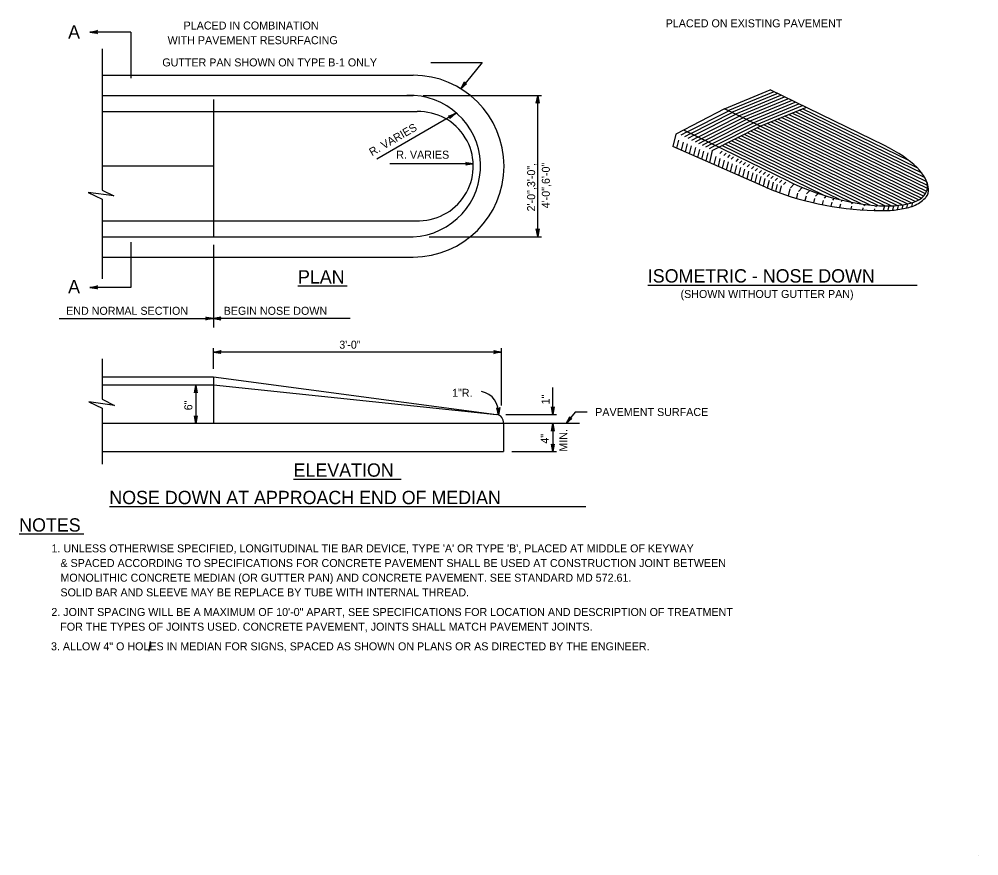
# Model space of a CAD drawing. Extents: x -7.6 to -0.4, y 98.1 to 108.3.
# Drawn here: x -7.55 to -0.36, y 98.11 to 104.38 of the extents above; entities that cross this region are included whole.
import ezdxf

# ---------------------------------------------------------------- set-up
doc = ezdxf.new("R2010")
doc.units = 0
for name, color, linetype in [('DETL-DIMS', 7, 'Continuous'), ('DETL-LINE', 7, 'Continuous'), ('DETL-NOTE', 7, 'Continuous'), ('DETL-PATT', 7, 'Continuous'), ('DETL-TITL', 7, 'Continuous'), ('TTLB-TEXT', 7, 'Continuous')]:
    doc.layers.add(name, color=color, linetype=linetype)

msp = doc.modelspace()

# ---------------------------------------------------------------- linework, layer by layer
at = {"layer": 'DETL-DIMS'}
for p, q in [((-6.7176, 104.2848), (-7.0248, 104.2848)), ((-6.7176, 104.2848), (-6.7176, 103.9375)), ((-4.4689, 104.0567), (-4.0849, 104.0567)), ((-4.0849, 104.0567), (-4.245, 103.8594)), ((-4.5276, 103.8092), (-3.6412, 103.8092)), ((-3.6685, 102.7486), (-3.6685, 103.8092)), ((-4.875, 103.3346), (-4.2738, 103.6817)), ((-4.1696, 103.2952), (-4.7761, 103.2952)), ((-4.4813, 102.7486), (-3.6412, 102.7486)), ((-6.7176, 102.7088), (-6.7176, 102.3698)), ((-6.0991, 102.688), (-6.0991, 102.0696)), ((-6.7176, 102.3698), (-7.0248, 102.3698)), ((-7.2552, 102.1357), (-6.0991, 102.1357)), ((-5.0737, 102.1357), (-6.0991, 102.1357)), ((-6.0991, 101.7591), (-6.0991, 101.9135)), ((-3.9396, 101.8843), (-6.0991, 101.8843)), ((-3.9396, 101.4848), (-3.9396, 101.9135)), ((-6.2305, 101.6379), (-6.2305, 101.35)), ((-3.555, 101.4168), (-3.555, 101.6185)), ((-3.3885, 101.4349), (-3.4563, 101.35)), ((-3.298, 101.4349), (-3.3885, 101.4349)), ((-3.9072, 101.4168), (-3.5278, 101.4168)), ((-3.555, 101.35), (-3.555, 101.1379)), ((-3.8636, 101.1379), (-3.5278, 101.1379))]:
    msp.add_line(p, q, dxfattribs=at)
for points in [[(-7.0248, 104.2848), (-6.9683, 104.2954), (-6.9727, 104.2924), (-6.9749, 104.2886), (-6.9755, 104.2848), (-6.9749, 104.2811), (-6.9727, 104.2773), (-6.9683, 104.2742), (-7.0248, 104.2848), (-6.9727, 104.2773), (-6.9749, 104.2811), (-7.0248, 104.2848), (-6.9755, 104.2848), (-6.9749, 104.2886), (-7.0248, 104.2848), (-6.9727, 104.2924)], [(-4.245, 103.8594), (-4.2176, 103.91), (-4.218, 103.9047), (-4.2165, 103.9006), (-4.214, 103.8977), (-4.2106, 103.8958), (-4.2063, 103.8951), (-4.2012, 103.8966), (-4.245, 103.8594), (-4.2063, 103.8951), (-4.2106, 103.8958), (-4.245, 103.8594), (-4.214, 103.8977), (-4.2165, 103.9006), (-4.245, 103.8594), (-4.218, 103.9047)], [(-3.6685, 103.8068), (-3.6579, 103.7503), (-3.6609, 103.7547), (-3.6647, 103.7569), (-3.6685, 103.7576), (-3.6723, 103.7569), (-3.676, 103.7547), (-3.6791, 103.7503), (-3.6685, 103.8068), (-3.676, 103.7547), (-3.6723, 103.7569), (-3.6685, 103.8068), (-3.6685, 103.7576), (-3.6647, 103.7569), (-3.6685, 103.8068), (-3.6609, 103.7547)], [(-4.2835, 103.6739), (-4.3271, 103.6364), (-4.3248, 103.6412), (-4.3248, 103.6456), (-4.3261, 103.6492), (-4.3285, 103.6522), (-4.3324, 103.6543), (-4.3377, 103.6548), (-4.2835, 103.6739), (-4.3324, 103.6543), (-4.3285, 103.6522), (-4.2835, 103.6739), (-4.3261, 103.6492), (-4.3248, 103.6456), (-4.2835, 103.6739), (-4.3248, 103.6412)], [(-4.1514, 103.295), (-4.208, 103.285), (-4.2036, 103.288), (-4.2013, 103.2918), (-4.2006, 103.2955), (-4.2012, 103.2993), (-4.2034, 103.3031), (-4.2077, 103.3062), (-4.1514, 103.295), (-4.2034, 103.3031), (-4.2012, 103.2993), (-4.1514, 103.295), (-4.2006, 103.2955), (-4.2013, 103.2918), (-4.1514, 103.295), (-4.2036, 103.288)], [(-3.6685, 102.751), (-3.6791, 102.8075), (-3.676, 102.8031), (-3.6723, 102.8009), (-3.6685, 102.8002), (-3.6647, 102.8009), (-3.6609, 102.8031), (-3.6579, 102.8075), (-3.6685, 102.751), (-3.6609, 102.8031), (-3.6647, 102.8009), (-3.6685, 102.751), (-3.6685, 102.8002), (-3.6723, 102.8009), (-3.6685, 102.751), (-3.676, 102.8031)], [(-7.0248, 102.3698), (-6.9683, 102.3804), (-6.9727, 102.3774), (-6.9749, 102.3736), (-6.9755, 102.3698), (-6.9749, 102.366), (-6.9727, 102.3622), (-6.9683, 102.3592), (-7.0248, 102.3698), (-6.9727, 102.3622), (-6.9749, 102.366), (-7.0248, 102.3698), (-6.9755, 102.3698), (-6.9749, 102.3736), (-7.0248, 102.3698), (-6.9727, 102.3774)], [(-6.0991, 102.1357), (-6.1556, 102.1251), (-6.1512, 102.1281), (-6.149, 102.1319), (-6.1483, 102.1357), (-6.149, 102.1395), (-6.1512, 102.1433), (-6.1556, 102.1463), (-6.0991, 102.1357), (-6.1512, 102.1433), (-6.149, 102.1395), (-6.0991, 102.1357), (-6.1483, 102.1357), (-6.149, 102.1319), (-6.0991, 102.1357), (-6.1512, 102.1281)], [(-6.0991, 102.1357), (-6.0426, 102.1251), (-6.0469, 102.1281), (-6.0492, 102.1319), (-6.0498, 102.1357), (-6.0492, 102.1395), (-6.0469, 102.1433), (-6.0426, 102.1463), (-6.0991, 102.1357), (-6.0469, 102.1433), (-6.0492, 102.1395), (-6.0991, 102.1357), (-6.0498, 102.1357), (-6.0492, 102.1319), (-6.0991, 102.1357), (-6.0469, 102.1281)], [(-6.0991, 101.8843), (-6.0426, 101.8949), (-6.0469, 101.8919), (-6.0492, 101.8881), (-6.0498, 101.8843), (-6.0492, 101.8805), (-6.0469, 101.8767), (-6.0426, 101.8737), (-6.0991, 101.8843), (-6.0469, 101.8767), (-6.0492, 101.8805), (-6.0991, 101.8843), (-6.0498, 101.8843), (-6.0492, 101.8881), (-6.0991, 101.8843), (-6.0469, 101.8919)], [(-3.9396, 101.8843), (-3.9961, 101.8737), (-3.9917, 101.8767), (-3.9895, 101.8805), (-3.9888, 101.8843), (-3.9895, 101.8881), (-3.9917, 101.8919), (-3.9961, 101.8949), (-3.9396, 101.8843), (-3.9917, 101.8919), (-3.9895, 101.8881), (-3.9396, 101.8843), (-3.9888, 101.8843), (-3.9895, 101.8805), (-3.9396, 101.8843), (-3.9917, 101.8767)], [(-6.2312, 101.6347), (-6.2206, 101.5782), (-6.2236, 101.5825), (-6.2274, 101.5848), (-6.2312, 101.5854), (-6.235, 101.5848), (-6.2388, 101.5825), (-6.2418, 101.5782), (-6.2312, 101.6347), (-6.2388, 101.5825), (-6.235, 101.5848), (-6.2312, 101.6347), (-6.2312, 101.5854), (-6.2274, 101.5848), (-6.2312, 101.6347), (-6.2236, 101.5825)], [(-3.9629, 101.4111), (-3.9746, 101.4673), (-3.9715, 101.463), (-3.9677, 101.4609), (-3.9639, 101.4603), (-3.9601, 101.461), (-3.9563, 101.4633), (-3.9534, 101.4678), (-3.9629, 101.4111), (-3.9563, 101.4633), (-3.9601, 101.461), (-3.9629, 101.4111), (-3.9639, 101.4603), (-3.9677, 101.4609), (-3.9629, 101.4111), (-3.9715, 101.463)], [(-3.555, 101.4168), (-3.5656, 101.4733), (-3.5626, 101.4689), (-3.5588, 101.4667), (-3.555, 101.466), (-3.5513, 101.4667), (-3.5475, 101.4689), (-3.5444, 101.4733), (-3.555, 101.4168), (-3.5475, 101.4689), (-3.5513, 101.4667), (-3.555, 101.4168), (-3.555, 101.466), (-3.5588, 101.4667), (-3.555, 101.4168), (-3.5626, 101.4689)], [(-6.2305, 101.3488), (-6.2411, 101.4053), (-6.238, 101.401), (-6.2343, 101.3987), (-6.2305, 101.3981), (-6.2267, 101.3987), (-6.2229, 101.401), (-6.2199, 101.4053), (-6.2305, 101.3488), (-6.2229, 101.401), (-6.2267, 101.3987), (-6.2305, 101.3488), (-6.2305, 101.3981), (-6.2343, 101.3987), (-6.2305, 101.3488), (-6.238, 101.401)], [(-3.555, 101.3478), (-3.5444, 101.2913), (-3.5475, 101.2957), (-3.5513, 101.2979), (-3.555, 101.2986), (-3.5588, 101.2979), (-3.5626, 101.2957), (-3.5656, 101.2913), (-3.555, 101.3478), (-3.5626, 101.2957), (-3.5588, 101.2979), (-3.555, 101.3478), (-3.555, 101.2986), (-3.5513, 101.2979), (-3.555, 101.3478), (-3.5475, 101.2957)], [(-3.4558, 101.349), (-3.4288, 101.3997), (-3.4292, 101.3944), (-3.4276, 101.3903), (-3.4251, 101.3874), (-3.4217, 101.3856), (-3.4173, 101.3849), (-3.4123, 101.3865), (-3.4558, 101.349), (-3.4173, 101.3849), (-3.4217, 101.3856), (-3.4558, 101.349), (-3.4251, 101.3874), (-3.4276, 101.3903), (-3.4558, 101.349), (-3.4292, 101.3944)], [(-3.555, 101.1379), (-3.5656, 101.1944), (-3.5626, 101.19), (-3.5588, 101.1878), (-3.555, 101.1871), (-3.5513, 101.1878), (-3.5475, 101.19), (-3.5444, 101.1944), (-3.555, 101.1379), (-3.5475, 101.19), (-3.5513, 101.1878), (-3.555, 101.1379), (-3.555, 101.1871), (-3.5588, 101.1878), (-3.555, 101.1379), (-3.5626, 101.19)]]:
    msp.add_lwpolyline(points, dxfattribs=at)
msp.add_arc((-4.1207, 101.4321), 0.1595, 352.48205, 78.94852, dxfattribs=at)
at = {"layer": 'DETL-LINE'}
for p, q in [((-6.9335, 104.1583), (-6.9335, 103.0982)), ((-6.9335, 103.9607), (-4.6025, 103.9607)), ((-6.9335, 103.8092), (-4.6025, 103.8092)), ((-2.2684, 103.7086), (-1.9269, 103.8502)), ((-1.0693, 103.4327), (-1.9269, 103.8502)), ((-6.0991, 103.7789), (-6.0991, 102.7486)), ((-6.9335, 103.688), (-4.5724, 103.688)), ((-2.2684, 103.7086), (-2.6333, 103.5175)), ((-0.8402, 103.0132), (-2.2684, 103.7086)), ((-2.0002, 103.5774), (-1.658, 103.7193)), ((-2.3598, 103.3957), (-2.0002, 103.5774)), ((-2.633, 103.5187), (-2.6556, 103.4262)), ((-1.7886, 103.1659), (-2.5742, 103.5484)), ((-1.9613, 103.12), (-2.6556, 103.4262)), ((-2.3598, 103.3957), (-2.3805, 103.3049)), ((-6.0991, 103.2789), (-6.9335, 103.2789)), ((-6.9335, 103.0317), (-6.9335, 102.4346)), ((-6.9335, 102.8698), (-4.5548, 102.8698)), ((-6.9335, 102.7486), (-4.6025, 102.7486)), ((-6.9335, 102.5971), (-4.6025, 102.5971)), ((-6.9335, 101.8335), (-6.9335, 101.5309)), ((-6.9335, 101.6985), (-6.0991, 101.6985)), ((-6.9335, 101.6379), (-6.0991, 101.6379)), ((-6.0991, 101.6985), (-6.0991, 101.35)), ((-6.0991, 101.6985), (-3.9779, 101.4168)), ((-6.0991, 101.6379), (-3.9779, 101.4168)), ((-6.9335, 101.4643), (-6.9335, 101.0445)), ((-6.9335, 101.35), (-3.9242, 101.35)), ((-3.9242, 101.35), (-3.9242, 101.1379)), ((-3.9242, 101.35), (-3.3557, 101.35)), ((-6.9335, 101.1379), (-3.9242, 101.1379))]:
    msp.add_line(p, q, dxfattribs=at)
for points in [[(-6.9335, 103.0982), (-6.8457, 103.0552), (-7.038, 103.0814), (-6.9335, 103.0317)], [(-6.9335, 101.5309), (-6.8395, 101.4849), (-7.0318, 101.5111), (-6.9335, 101.4643)]]:
    msp.add_lwpolyline(points, dxfattribs=at)
for centre, radius, start, end in [((-4.6025, 103.2789), 0.6818, 270, 90), ((-4.6279, 103.2789), 0.5309, 272.73522, 92.25876), ((-4.5605, 103.2789), 0.4092, 270.79899, 91.6738), ((-3.9848, 101.3566), 0.0606, 353.78359, 83.44779)]:
    msp.add_arc(centre, radius, start, end, dxfattribs=at)
for centre, major_axis, ratio, start_param, end_param in [((-1.4282, 103.2989), (0.6779, -0.2029), 0.361972, 4.263313, 7.407609), ((-1.2999, 103.8155), (-1.4065, 0.2165), 0.6, 1.175606, 1.771615)]:
    msp.add_ellipse(centre, major_axis=major_axis, ratio=ratio, start_param=start_param, end_param=end_param, dxfattribs=at)
msp.add_spline([(-1.1467, 102.9454), (-1.0099, 102.9482), (-0.9003, 102.9664), (-0.8046, 103.0058), (-0.7652, 103.0397), (-0.7558, 103.049), (-0.7389, 103.1092), (-0.7524, 103.1607)], degree=3, dxfattribs=at)
at = {"layer": 'DETL-NOTE'}
for p, q in [((-2.8435, 102.3872), (-0.8241, 102.3872)), ((-5.4989, 100.931), (-4.6931, 100.931)), ((-6.8784, 100.7252), (-3.3089, 100.7252)), ((-7.555, 100.5206), (-7.0704, 100.5206)), ((-6.5807, 99.6417), (-6.5711, 99.7148))]:
    msp.add_line(p, q, dxfattribs=at)
at = {"layer": 'DETL-PATT'}
for p, q in [((-2.2415, 103.6955), (-1.9, 103.8371)), ((-2.2146, 103.6824), (-1.8731, 103.824)), ((-2.1877, 103.6693), (-1.8462, 103.8109)), ((-2.1608, 103.6562), (-1.8193, 103.7978)), ((-2.1339, 103.6431), (-1.7924, 103.7847)), ((-2.1071, 103.63), (-1.7655, 103.7716)), ((-2.0802, 103.6169), (-1.7387, 103.7586)), ((-2.0533, 103.6038), (-1.7118, 103.7455)), ((-2.0264, 103.5908), (-1.6849, 103.7324)), ((-2.5479, 103.5356), (-2.2363, 103.693)), ((-2.5216, 103.5228), (-2.21, 103.6802)), ((-2.4953, 103.51), (-2.1837, 103.6674)), ((-2.469, 103.4972), (-2.1574, 103.6546)), ((-0.7469, 103.1342), (-1.815, 103.6542)), ((-0.7524, 103.1607), (-1.7886, 103.6651)), ((-0.7653, 103.1907), (-1.7622, 103.6761)), ((-0.7877, 103.2253), (-1.7359, 103.687)), ((-0.8241, 103.2668), (-1.7095, 103.6979)), ((-0.8863, 103.3209), (-1.6831, 103.7089)), ((-2.4427, 103.4844), (-2.1311, 103.6417)), ((-2.4163, 103.4716), (-2.1048, 103.6289)), ((-2.39, 103.4588), (-2.0785, 103.6161)), ((-2.3637, 103.446), (-2.0522, 103.6033)), ((-2.3374, 103.4332), (-2.0259, 103.5905)), ((-0.8153, 103.0249), (-1.9732, 103.5886)), ((-0.794, 103.0383), (-1.9468, 103.5995)), ((-0.7763, 103.0534), (-1.9204, 103.6105)), ((-0.7624, 103.0704), (-1.894, 103.6214)), ((-0.7526, 103.0894), (-1.8677, 103.6323)), ((-0.7472, 103.1106), (-1.8413, 103.6433)), ((-2.5479, 103.5356), (-2.5946, 103.5107)), ((-2.5216, 103.5228), (-2.5683, 103.4979)), ((-2.4953, 103.51), (-2.542, 103.4851)), ((-1.0662, 102.9806), (-2.1434, 103.5051)), ((-1.0184, 102.9811), (-2.1194, 103.5172)), ((-0.9751, 102.9838), (-2.0954, 103.5293)), ((-0.9359, 102.9884), (-2.0715, 103.5414)), ((-0.9004, 102.9949), (-2.0475, 103.5535)), ((-0.8685, 103.0032), (-2.0235, 103.5656)), ((-2.6136, 103.4743), (-2.6283, 103.4142)), ((-2.5788, 103.4589), (-2.5934, 103.3988)), ((-2.5481, 103.4454), (-2.5628, 103.3853)), ((-2.469, 103.4972), (-2.5157, 103.4723)), ((-2.4427, 103.4844), (-2.4893, 103.4595)), ((-2.4163, 103.4716), (-2.463, 103.4467)), ((-2.39, 103.4588), (-2.4367, 103.4339)), ((-2.3637, 103.446), (-2.4104, 103.4211)), ((-2.3374, 103.4332), (-2.3841, 103.4083)), ((-1.5212, 103.0595), (-2.2872, 103.4324)), ((-1.4075, 103.0279), (-2.2632, 103.4446)), ((-1.3185, 103.0084), (-2.2392, 103.4567)), ((-1.2434, 102.9956), (-2.2153, 103.4688)), ((-1.1776, 102.9873), (-2.1913, 103.4809)), ((-1.1189, 102.9825), (-2.1673, 103.493)), ((-2.5174, 103.4318), (-2.532, 103.3717)), ((-2.4867, 103.4183), (-2.5013, 103.3582)), ((-2.4559, 103.4047), (-2.4706, 103.3446)), ((-2.4252, 103.3912), (-2.4399, 103.3311)), ((-2.3945, 103.3776), (-2.4086, 103.3198)), ((-2.2865, 103.3915), (-2.304, 103.3733)), ((-2.2562, 103.3767), (-2.2737, 103.3585)), ((-2.2274, 103.3627), (-2.2449, 103.3445)), ((-2.333, 103.3505), (-2.3477, 103.2904)), ((-2.3023, 103.337), (-2.317, 103.2769)), ((-2.2716, 103.3234), (-2.2862, 103.2633)), ((-2.2409, 103.3099), (-2.2555, 103.2498)), ((-2.2101, 103.2963), (-2.2248, 103.2362)), ((-2.2008, 103.3497), (-2.2183, 103.3316)), ((-2.1662, 103.3329), (-2.1837, 103.3147)), ((-2.1379, 103.3191), (-2.1553, 103.3009)), ((-2.1102, 103.3056), (-2.1277, 103.2874)), ((-2.0812, 103.2915), (-2.0986, 103.2733)), ((-2.1794, 103.2828), (-2.1941, 103.2227)), ((-2.1487, 103.2692), (-2.1633, 103.2091)), ((-2.118, 103.2557), (-2.1327, 103.1956)), ((-2.0873, 103.2421), (-2.1019, 103.1821)), ((-2.0566, 103.2286), (-2.0713, 103.1685)), ((-2.0497, 103.2761), (-2.0672, 103.258)), ((-2.0213, 103.2623), (-2.0388, 103.2442)), ((-1.9905, 103.2473), (-2.008, 103.2292)), ((-1.9615, 103.2332), (-1.979, 103.215)), ((-1.9311, 103.2184), (-1.9486, 103.2003)), ((-2.0258, 103.215), (-2.0405, 103.1549)), ((-1.9951, 103.2015), (-2.0098, 103.1414)), ((-1.965, 103.1852), (-1.979, 103.1278)), ((-1.9346, 103.1704), (-1.9483, 103.1146)), ((-1.9028, 103.2046), (-1.9203, 103.1864)), ((-1.9036, 103.1583), (-1.9173, 103.1021)), ((-1.8713, 103.1893), (-1.8888, 103.1711)), ((-1.8398, 103.174), (-1.8573, 103.1558)), ((-1.8097, 103.1593), (-1.8272, 103.1411)), ((-1.7469, 103.1459), (-1.7748, 103.1168)), ((-1.8738, 103.1408), (-1.8862, 103.0901)), ((-1.8425, 103.13), (-1.855, 103.0787)), ((-1.7795, 103.1096), (-1.7923, 103.0573)), ((-1.72, 103.0751), (-1.7291, 103.0379)), ((-1.6853, 103.1188), (-1.7138, 103.0893)), ((-1.6286, 103.0964), (-1.6527, 103.0713)), ((-1.5664, 103.0742), (-1.5871, 103.0526)), ((-1.6572, 103.0543), (-1.6655, 103.0203)), ((-1.5934, 103.0371), (-1.6013, 103.0045)), ((-1.5297, 103.0199), (-1.5368, 102.9906)), ((-1.5074, 103.0553), (-1.5225, 103.0396)), ((-1.4644, 103.0088), (-1.4718, 102.9785)), ((-1.4454, 103.0376), (-1.4586, 103.0239)), ((-1.3848, 103.0225), (-1.3934, 103.0136)), ((-1.3072, 103.0047), (-1.3158, 102.9958)), ((-0.8597, 103.006), (-0.8671, 102.9756)), ((-1.4001, 102.9936), (-1.4064, 102.9681)), ((-1.3158, 102.9774), (-1.3207, 102.9574)), ((-1.2303, 102.9654), (-1.2341, 102.9498)), ((-1.2144, 102.9897), (-1.223, 102.9807)), ((-1.1435, 102.9586), (-1.1467, 102.9454)), ((-1.1289, 102.9824), (-1.1375, 102.9735)), ((-1.07, 102.9807), (-1.0783, 102.9468)), ((-1.036, 102.9807), (-1.0441, 102.9475)), ((-1.0017, 102.9819), (-1.0099, 102.9482)), ((-0.967, 102.9846), (-0.9752, 102.951)), ((-0.9319, 102.9891), (-0.9396, 102.9573)), ((-0.8962, 102.9959), (-0.9036, 102.9656))]:
    msp.add_line(p, q, dxfattribs=at)
at = {"layer": 'DETL-TITL'}
msp.add_line((-5.4655, 102.3799), (-5.0958, 102.3799), dxfattribs=at)
at = {"layer": 'TTLB-TEXT'}
msp.add_line((-0.3622, 98.1063), (-0.3622, 98.1063), dxfattribs=at)

# ---------------------------------------------------------------- texts
at = {"layer": 'DETL-NOTE'}
for s, height, p in [('PLACED ON EXISTING PAVEMENT', 0.06, (-2.7091, 104.3201)), ('A', 0.1, (-7.1883, 104.2351)), ('PLACED IN COMBINATION', 0.06, (-6.3225, 104.3034)), ('WITH PAVEMENT RESURFACING', 0.06, (-6.4425, 104.1934)), ('GUTTER PAN SHOWN ON TYPE B-1 ONLY', 0.06, (-6.4822, 104.0267)), ('R. VARIES', 0.06, (-4.7286, 103.3346)), ('A', 0.1, (-7.1883, 102.3256)), ('(SHOWN WITHOUT GUTTER PAN)', 0.06, (-2.5978, 102.2901)), ('END NORMAL SECTION', 0.06, (-7.2031, 102.1638)), ('BEGIN NOSE DOWN', 0.06, (-6.0223, 102.1638)), ('3\'-0"', 0.06, (-5.1557, 101.9097)), ('1"R.', 0.06, (-4.3102, 101.5487)), ('PAVEMENT SURFACE', 0.06, (-3.2374, 101.4049)), ('NOTES', 0.1, (-7.5549, 100.5377)), ("1. UNLESS OTHERWISE SPECIFIED, LONGITUDINAL TIE BAR DEVICE, TYPE 'A' OR TYPE 'B', PLACED AT MIDDLE OF KEYWAY", 0.06, (-7.3127, 100.3821)), ('   & SPACED ACCORDING TO SPECIFICATIONS FOR CONCRETE PAVEMENT SHALL BE USED AT CONSTRUCTION JOINT BETWEEN', 0.06, (-7.3127, 100.2721)), ('   MONOLITHIC CONCRETE MEDIAN (OR GUTTER PAN) AND CONCRETE PAVEMENT. SEE STANDARD MD 572.61. ', 0.06, (-7.3127, 100.1621)), ('   SOLID BAR AND SLEEVE MAY BE REPLACE BY TUBE WITH INTERNAL THREAD. ', 0.06, (-7.3127, 100.0521)), ('2. JOINT SPACING WILL BE A MAXIMUM OF 10\'-0" APART, SEE SPECIFICATIONS FOR LOCATION AND DESCRIPTION OF TREATMENT', 0.06, (-7.314, 99.9048)), ('   FOR THE TYPES OF JOINTS USED. CONCRETE PAVEMENT, JOINTS SHALL MATCH PAVEMENT JOINTS.', 0.06, (-7.314, 99.7948)), ('3. ALLOW 4" O HOLES IN MEDIAN FOR SIGNS, SPACED AS SHOWN ON PLANS OR AS DIRECTED BY THE ENGINEER.', 0.06, (-7.3166, 99.6475))]:
    msp.add_text(s, height=height, dxfattribs=at).set_placement(p)
for s, rotation, p in [('R. VARIES', 30.1029, (-4.9103, 103.3525)), ('2\'-0",3\'-0",', 90, (-3.6876, 102.9392)), ('4\'-0",6\'-0"', 90, (-3.5776, 102.9625)), ('1"', 90, (-3.5797, 101.4922)), ('6"', 90, (-6.2574, 101.4476)), ('MIN.', 90, (-3.4472, 101.1374)), ('4"', 90, (-3.5855, 101.1976))]:
    msp.add_text(s, height=0.06, rotation=rotation, dxfattribs=at).set_placement(p)
at = {"layer": 'DETL-TITL'}
for s, p in [('PLAN', (-5.4653, 102.3985)), ('ISOMETRIC - NOSE DOWN', (-2.8432, 102.4058)), ('ELEVATION', (-5.4984, 100.9496)), ('NOSE DOWN AT APPROACH END OF MEDIAN', (-6.8794, 100.7438))]:
    msp.add_text(s, height=0.1, dxfattribs=at).set_placement(p)

doc.saveas('drawing.dxf')
